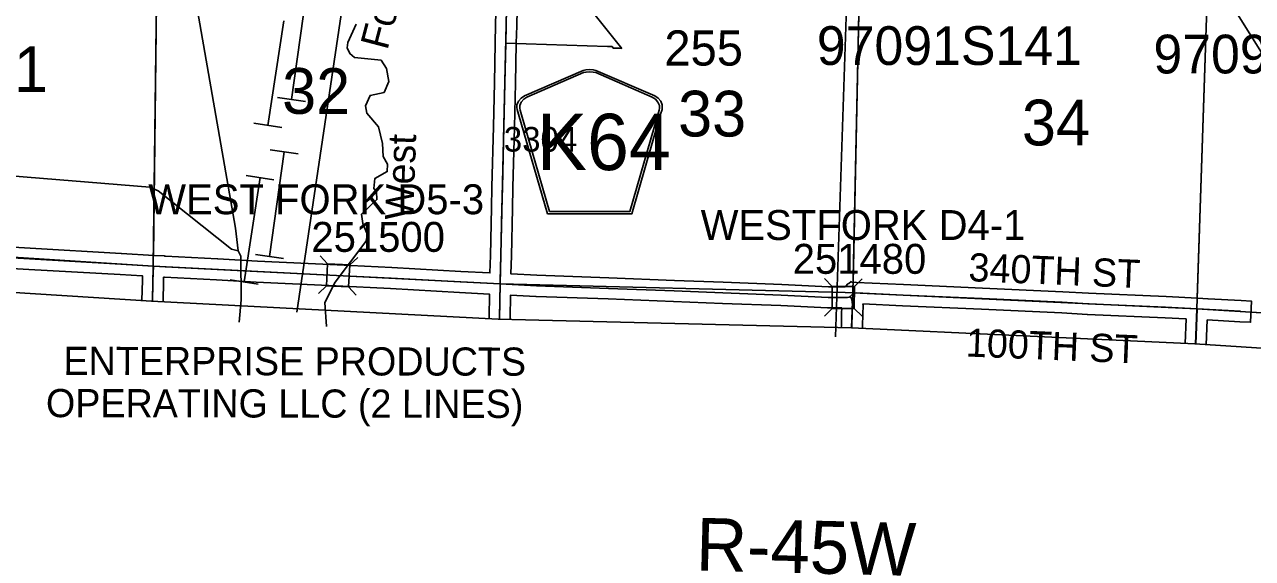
# Model space of a CAD drawing. Extents: x -157.2 to -99.3, y 12.2 to 46.2.
# Drawn here: x -134.532 to -131.046, y 15.921 to 17.437 of the extents above; entities that cross this region are included whole.
import ezdxf

# ---------------------------------------------------------------- set-up
doc = ezdxf.new("R2010")
doc.units = 0
for name, color, linetype in [('tdCoClipBndry', 7, 'Continuous'), ('tdCoCoAdjSecRdTxt', 7, 'Continuous'), ('tdCoCoBndry', 7, 'Continuous'), ('tdCoCoBndryPart', 7, 'Continuous'), ('tdCoCorpBndry', 7, 'Continuous'), ('tdCoCorpPopTxt', 7, 'Continuous'), ('tdCoHydroRiver', 7, 'Continuous'), ('tdCoHydroTxtLg', 7, 'Continuous'), ('tdCoPipe', 7, 'Continuous'), ('tdCoPipe1', 7, 'Continuous'), ('tdCoPipe2', 7, 'Continuous'), ('tdCoPipeTxt', 7, 'Continuous'), ('tdCoSecRdNmbr', 7, 'Continuous'), ('tdCoSecRdTxt', 7, 'Continuous'), ('tdCoSecRteBand', 7, 'Continuous'), ('tdCoSecRteCL', 7, 'Continuous'), ('tdCoSectLine', 7, 'Continuous'), ('tdCoSectLinePart', 7, 'Continuous'), ('tdCoSectNmbr', 7, 'Continuous'), ('tdCoShieldCoRteHrd', 7, 'Continuous'), ('tdCoStrucPriMaintName', 7, 'Continuous'), ('tdCoStrucSec', 7, 'Continuous'), ('tdCoStrucSecCoName', 7, 'Continuous'), ('tdCoStrucSecFHWANum', 7, 'Continuous'), ('tdCoSurfAsphalt', 7, 'Continuous'), ('tdCoSurfConc', 7, 'Continuous'), ('tdCoSurfEarth', 7, 'Continuous'), ('tdCoSurfGravel', 7, 'Continuous'), ('tdCoTwpBndryShd', 7, 'Continuous'), ('tdCoTwpRngTxt', 7, 'Continuous')]:
    doc.layers.add(name, color=color, linetype=linetype)

msp = doc.modelspace()

# ---------------------------------------------------------------- linework, layer by layer
at = {"layer": 'tdCoClipBndry'}
msp.add_lwpolyline([(-122.302, 16.1905), (-125.2749, 16.2789), (-127.2441, 16.3602), (-128.2341, 16.3892), (-129.2216, 16.4019), (-131.209, 16.5298), (-132.1838, 16.5754), (-133.1873, 16.6004), (-134.1718, 16.6514), (-135.1611, 16.7141)], dxfattribs=at)
at = {"layer": 'tdCoCoBndry'}
msp.add_lwpolyline([(-135.1553, 16.8138), (-134.1666, 16.7512), (-133.1821, 16.7002), (-132.2019, 16.6758), (-132.1802, 16.6753), (-131.2035, 16.6296), (-130.2056, 16.5679), (-129.2203, 16.5019), (-128.232, 16.4892), (-127.2406, 16.4601), (-126.2534, 16.4199), (-125.2718, 16.3788), (-124.2853, 16.348)], dxfattribs=at)
at = {"layer": 'tdCoCoBndryPart'}
msp.add_lwpolyline([(-131.0502, 16.6201), (-130.2056, 16.5679), (-129.6683, 16.5319)], dxfattribs=at)
at = {"layer": 'tdCoCorpBndry'}
msp.add_lwpolyline([(-132.8359, 17.3694), (-132.8426, 17.3696), (-132.8607, 17.3701), (-132.8642, 17.3744), (-132.8768, 17.3749), (-133.1659, 17.3844), (-133.1648, 17.4345), (-133.1625, 17.5325), (-133.1605, 17.6197), (-133.1601, 17.6388), (-133.1539, 17.6384), (-133.1371, 17.6477), (-133.0754, 17.6385), (-133.049, 17.6358)], close=True, dxfattribs=at)
at = {"layer": 'tdCoHydroRiver'}
for points in [[(-132.2292, 16.5498), (-132.1404, 19.2211)], [(-131.1696, 19.1917), (-131.1706, 18.9975), (-131.1548, 18.0351), (-131.1479, 17.6289), (-131.1402, 17.5702), (-131.1299, 17.5431), (-131.1208, 17.5318), (-131.1211, 17.5207), (-131.0201, 17.3581), (-130.8557, 17.1036), (-130.8545, 17.0925), (-130.8001, 17.0118), (-130.7907, 17.0084)], [(-134.107, 17.8578), (-133.9334, 16.8591), (-133.9258, 16.7941)], [(-133.6753, 16.5796), (-133.6793, 16.6476), (-133.6507, 16.7052), (-133.5636, 16.821), (-133.5582, 16.8398), (-133.5715, 16.8718), (-133.5754, 16.8987), (-133.5316, 16.94), (-133.5325, 16.9622), (-133.5401, 16.9719), (-133.5376, 17.0002), (-133.5023, 17.0197), (-133.5017, 17.0402), (-133.5137, 17.0627), (-133.5157, 17.0991), (-133.5269, 17.1468), (-133.5605, 17.1857), (-133.5646, 17.2064), (-133.5511, 17.236), (-133.5114, 17.2443), (-133.4978, 17.2754), (-133.5046, 17.312), (-133.5197, 17.3361), (-133.5952, 17.3431), (-133.6091, 17.3546), (-133.6165, 17.3706), (-133.6144, 17.3864), (-133.5908, 17.4378)], [(-134.6184, 17.0108), (-134.1761, 16.9754), (-134.1527, 16.9652), (-133.9446, 16.7994), (-133.9258, 16.7941)], [(-133.9258, 16.7941), (-133.9184, 16.7796), (-133.9174, 16.6548), (-133.9233, 16.5915)]]:
    msp.add_lwpolyline(points, dxfattribs=at)
at = {"layer": 'tdCoPipe'}
msp.add_lwpolyline([(-133.759, 16.6205), (-133.5865, 17.7778), (-133.4655, 18.0471), (-133.3685, 18.1297), (-133.2951, 18.596), (-133.1374, 20.0968), (-132.9167, 20.1674), (-132.8765, 20.8382), (-131.6756, 21.8898), (-131.4423, 22.6481), (-130.9379, 23.6667), (-130.3462, 24.8998), (-130.3405, 25.1948), (-130.2487, 25.3673), (-130.2364, 26.2904), (-130.2373, 27.9658), (-130.2301, 29.1582), (-130.2142, 30.4341), (-130.1913, 32.2243), (-130.16, 33.6013), (-130.1464, 33.8322), (-130.2014, 34.2309), (-130.2039, 34.9469)], dxfattribs=at)
at = {"layer": 'tdCoPipe1'}
for p, q in [((-133.8808, 17.1568), (-133.8015, 17.1448)), ((-133.9033, 17.0085), (-133.824, 16.9964)), ((-133.9483, 16.7119), (-133.869, 16.6998))]:
    msp.add_line(p, q, dxfattribs=at)
for points in [[(-133.7961, 17.4474), (-133.8411, 17.1508)], [(-133.8636, 17.0025), (-133.9086, 16.7059)]]:
    msp.add_lwpolyline(points, dxfattribs=at)
at = {"layer": 'tdCoPipe2'}
for p, q in [((-133.814, 17.2298), (-133.7346, 17.2186)), ((-133.835, 17.0813), (-133.7556, 17.0701)), ((-133.8768, 16.7842), (-133.7974, 16.773))]:
    msp.add_line(p, q, dxfattribs=at)
for points in [[(-133.7325, 17.5213), (-133.7743, 17.2242)], [(-133.7953, 17.0757), (-133.8371, 16.7786)]]:
    msp.add_lwpolyline(points, dxfattribs=at)
at = {"layer": 'tdCoSecRteBand'}
for points in [[(-134.7125, 16.813), (-134.5166, 16.8017), (-134.5166, 16.8017), (-134.5166, 16.8017), (-134.2575, 16.7866), (-134.2574, 16.7866), (-134.2574, 16.7866), (-134.1649, 16.7812), (-134.1353, 16.7802), (-134.1353, 16.7795), (-134.1318, 16.7793), (-133.9839, 16.7716), (-133.9839, 16.7716), (-133.9838, 16.7716), (-133.8712, 16.7654), (-133.6447, 16.7546), (-133.4898, 16.7472), (-133.4897, 16.7472), (-133.4895, 16.7472), (-133.2938, 16.7359), (-133.211, 16.7317), (-133.2097, 16.7814), (-133.2067, 16.9162), (-133.2054, 16.9752), (-133.2054, 16.9752), (-133.2054, 16.9753), (-133.2011, 17.1471), (-133.1983, 17.2717), (-133.1959, 17.3847), (-133.1959, 17.3847), (-133.1959, 17.385), (-133.1948, 17.4351), (-133.1948, 17.4351), (-133.1948, 17.4352), (-133.1905, 17.6204)], [(-133.1305, 17.619), (-133.1348, 17.4338), (-133.1359, 17.3841), (-133.1359, 17.3841), (-133.1359, 17.3837), (-133.1384, 17.2704), (-133.1384, 17.2704), (-133.1384, 17.2704), (-133.1412, 17.1457), (-133.1412, 17.1456), (-133.1412, 17.1456), (-133.1455, 16.9739), (-133.1467, 16.9149), (-133.1467, 16.9148), (-133.1467, 16.9148), (-133.1498, 16.78), (-133.1498, 16.78), (-133.1498, 16.7799), (-133.1511, 16.7287), (-133.1502, 16.7287), (-133.0776, 16.725), (-132.8732, 16.7176), (-132.8731, 16.7176), (-132.8731, 16.7176), (-132.6869, 16.7105), (-132.6869, 16.7105), (-132.6869, 16.7105), (-132.5483, 16.705), (-132.3823, 16.6986), (-132.3822, 16.6986), (-132.3821, 16.6986), (-132.2498, 16.6922), (-132.2031, 16.692), (-132.2008, 16.6943), (-132.1944, 16.7007), (-132.1918, 16.7012), (-132.1849, 16.7072), (-132.1825, 16.7045), (-132.1796, 16.7064), (-132.178, 16.704), (-132.1772, 16.7042), (-132.1735, 16.705), (-132.1697, 16.7048), (-132.0364, 16.6984), (-131.8123, 16.6888), (-131.8123, 16.6888), (-131.8122, 16.6888), (-131.5846, 16.6782), (-131.5844, 16.6781), (-131.5843, 16.6781), (-131.5117, 16.674), (-131.291, 16.6644), (-131.2908, 16.6643), (-131.2907, 16.6643), (-131.2017, 16.6596), (-131.172, 16.6584), (-131.172, 16.658), (-131.0781, 16.653), (-131.0481, 16.6514), (-131.0513, 16.5915), (-131.0813, 16.5931), (-131.1743, 16.598), (-131.177, 16.5277)], [(-134.199, 16.6531), (-134.1976, 16.7109), (-134.1976, 16.711), (-134.1976, 16.7112), (-134.1972, 16.723), (-134.1979, 16.723), (-134.2609, 16.7267), (-134.5201, 16.7418), (-134.7162, 16.7531)], [(-133.2134, 16.6017), (-133.2133, 16.6055), (-133.2122, 16.6717), (-133.297, 16.6759), (-133.2971, 16.6759), (-133.2972, 16.6759), (-133.4928, 16.6873), (-133.6476, 16.6947), (-133.6476, 16.6947), (-133.8742, 16.7055), (-133.8743, 16.7055), (-133.8744, 16.7055), (-133.9871, 16.7117), (-134.135, 16.7193), (-134.1351, 16.7193), (-134.1352, 16.7193), (-134.1373, 16.7195), (-134.1376, 16.7093), (-134.1391, 16.6497)], [(-132.2134, 16.5761), (-132.2131, 16.5815), (-132.2124, 16.6169), (-132.2124, 16.6172), (-132.2124, 16.6176), (-132.2118, 16.6321), (-132.2507, 16.6322), (-132.2514, 16.6322), (-132.252, 16.6323), (-132.3848, 16.6387), (-132.5506, 16.6451), (-132.5506, 16.6451), (-132.5506, 16.6451), (-132.6892, 16.6505), (-132.8754, 16.6577), (-133.08, 16.6651), (-133.0802, 16.6651), (-133.0804, 16.6651), (-133.1522, 16.6687), (-133.1533, 16.6043), (-133.1533, 16.6042), (-133.1533, 16.6041), (-133.1534, 16.5995)], [(-131.2369, 16.5311), (-131.2342, 16.6012), (-131.2347, 16.6013), (-131.2937, 16.6044), (-131.5145, 16.614), (-131.5147, 16.614), (-131.515, 16.614), (-131.5875, 16.6182), (-131.8149, 16.6288), (-132.039, 16.6384), (-132.0391, 16.6384), (-132.0392, 16.6384), (-132.1516, 16.6438), (-132.1515, 16.6411), (-132.1514, 16.6398), (-132.1514, 16.6385), (-132.1524, 16.6154), (-132.1532, 16.5799), (-132.1532, 16.5796), (-132.1532, 16.5792), (-132.1534, 16.574)]]:
    msp.add_lwpolyline(points, dxfattribs=at)
at = {"layer": 'tdCoSecRteCL'}
for p, q in [((-131.207, 16.5297), (-131.2031, 16.6296)), ((-131.2031, 16.6296), (-131.0797, 16.623))]:
    msp.add_line(p, q, dxfattribs=at)
for points in [[(-133.1817, 16.7002), (-133.1815, 16.7103), (-133.1798, 16.7807), (-133.1767, 16.9155), (-133.1754, 16.9745), (-133.1711, 17.1464), (-133.1684, 17.271), (-133.1659, 17.3844), (-133.1659, 17.3844), (-133.1648, 17.4345), (-133.1605, 17.6197), (-133.1601, 17.6388), (-133.1596, 17.6635), (-133.1583, 17.7272), (-133.1558, 17.8267), (-133.1553, 17.8476), (-133.1536, 17.9159), (-133.1519, 17.9877), (-133.1516, 17.997), (-133.1506, 18.0482), (-133.1504, 18.0533), (-133.149, 18.0886), (-133.1473, 18.1331), (-133.146, 18.1781)], [(-136.1292, 16.8661), (-136.0182, 16.86), (-135.7743, 16.8465), (-135.6318, 16.8388), (-135.4777, 16.8309), (-135.2594, 16.8203), (-135.1525, 16.8137), (-135.108, 16.8109), (-134.7144, 16.7831), (-134.5184, 16.7717), (-134.2592, 16.7567), (-134.1662, 16.7512)], [(-134.169, 16.6513), (-134.1676, 16.7102), (-134.1662, 16.7512)], [(-134.1662, 16.7512), (-134.1334, 16.7493), (-133.9855, 16.7417), (-133.8728, 16.7355), (-133.6461, 16.7246), (-133.4913, 16.7172), (-133.2955, 16.7059), (-133.1817, 16.7002)], [(-133.1834, 16.6003), (-133.1833, 16.6048), (-133.1817, 16.7002)], [(-133.1817, 16.7002), (-133.0789, 16.695), (-132.8743, 16.6876), (-132.6881, 16.6805), (-132.5495, 16.6751), (-132.3835, 16.6687), (-132.2506, 16.6622), (-132.1958, 16.662), (-132.1909, 16.6625), (-132.1881, 16.6649)], [(-132.1881, 16.6649), (-132.1857, 16.6669), (-132.1796, 16.6731), (-132.1712, 16.6748), (-132.0378, 16.6684), (-131.8136, 16.6588), (-131.586, 16.6482), (-131.5132, 16.644), (-131.2923, 16.6344), (-131.2031, 16.6296)], [(-132.1834, 16.5754), (-132.1831, 16.5805), (-132.1824, 16.6163), (-132.1814, 16.6397), (-132.1819, 16.6506), (-132.1844, 16.6585), (-132.1864, 16.6622), (-132.1881, 16.6649)]]:
    msp.add_lwpolyline(points, dxfattribs=at)
at = {"layer": 'tdCoSectLine'}
for points in [[(-134.1666, 16.7512), (-134.1544, 17.7403)], [(-133.1595, 17.684), (-133.1821, 16.7002)], [(-132.1802, 16.6753), (-132.16, 17.6471)], [(-131.2035, 16.6296), (-131.1717, 17.6002)], [(-135.1553, 16.8138), (-134.1666, 16.7512)], [(-134.1691, 16.6513), (-134.1666, 16.7512)], [(-134.1666, 16.7512), (-133.1821, 16.7002)], [(-133.1841, 16.6003), (-133.1821, 16.7002)], [(-133.1821, 16.7002), (-132.2019, 16.6758), (-132.1802, 16.6753)], [(-132.1847, 16.5754), (-132.1802, 16.6753)], [(-132.1802, 16.6753), (-131.2035, 16.6296)], [(-131.2074, 16.5297), (-131.2035, 16.6296)], [(-131.2035, 16.6296), (-130.2056, 16.5679)]]:
    msp.add_lwpolyline(points, dxfattribs=at)
at = {"layer": 'tdCoSectLinePart'}
for points in [[(-134.1662, 16.7812), (-134.1544, 17.7403)], [(-132.1796, 16.7031), (-132.16, 17.6471)], [(-131.2025, 16.6596), (-131.1717, 17.6002)], [(-131.0502, 16.6201), (-130.2056, 16.5679)]]:
    msp.add_lwpolyline(points, dxfattribs=at)
at = {"layer": 'tdCoShieldCoRteHrd'}
for points in [[(-133.0475, 16.8994), (-133.1295, 17.1823), (-133.1334, 17.1954), (-133.1341, 17.2013), (-133.1341, 17.2091), (-133.1299, 17.2195), (-133.1226, 17.2279), (-133.113, 17.2346), (-132.9457, 17.307), (-132.9382, 17.3086), (-132.9278, 17.3095), (-132.9174, 17.3086), (-132.9098, 17.307), (-132.7426, 17.2346), (-132.733, 17.2279), (-132.7257, 17.2195), (-132.7215, 17.2091), (-132.7215, 17.2013), (-132.7222, 17.1954), (-132.7261, 17.1823), (-132.808, 16.8994)], [(-133.0417, 16.9057), (-133.1214, 17.181), (-133.1251, 17.1936), (-133.1258, 17.1993), (-133.1258, 17.2068), (-133.1218, 17.2167), (-133.1148, 17.2248), (-133.1056, 17.2312), (-132.945, 17.3007), (-132.9378, 17.3023), (-132.9278, 17.3031), (-132.9178, 17.3023), (-132.9106, 17.3007), (-132.75, 17.2312), (-132.7408, 17.2248), (-132.7338, 17.2167), (-132.7297, 17.2068), (-132.7297, 17.1993), (-132.7304, 17.1936), (-132.7342, 17.181), (-132.8139, 16.9057)]]:
    msp.add_lwpolyline(points, close=True, dxfattribs=at)
at = {"layer": 'tdCoStrucSec'}
for p, q in [((-133.6716, 16.7572), (-133.6926, 16.7803)), ((-133.609, 16.7542), (-133.5859, 16.7752)), ((-132.2387, 16.6935), (-132.2608, 16.7157)), ((-132.1761, 16.6932), (-132.1539, 16.7152)), ((-133.6745, 16.6946), (-133.6977, 16.6736)), ((-133.612, 16.6917), (-133.591, 16.6685)), ((-132.239, 16.6309), (-132.2612, 16.6089)), ((-132.1764, 16.6306), (-132.1544, 16.6084))]:
    msp.add_line(p, q, dxfattribs=at)
for points in [[(-133.6716, 16.7572), (-133.609, 16.7542), (-133.612, 16.6917), (-133.6745, 16.6946)], [(-132.2387, 16.6935), (-132.1761, 16.6932), (-132.1764, 16.6306), (-132.239, 16.6309)]]:
    msp.add_lwpolyline(points, close=True, dxfattribs=at)
at = {"layer": 'tdCoSurfAsphalt'}
msp.add_lwpolyline([(-133.1834, 16.6003), (-133.1833, 16.6048), (-133.1817, 16.7002)], dxfattribs=at)
at = {"layer": 'tdCoSurfConc'}
msp.add_line((-133.1659, 17.3844), (-133.1659, 17.3844), dxfattribs=at)
for points in [[(-133.1659, 17.3844), (-133.1648, 17.4345), (-133.1605, 17.6197), (-133.1601, 17.6388)], [(-133.1817, 16.7002), (-133.1815, 16.7103), (-133.1798, 16.7807), (-133.1767, 16.9155), (-133.1754, 16.9745), (-133.1711, 17.1464), (-133.1684, 17.271), (-133.1659, 17.3844)]]:
    msp.add_lwpolyline(points, dxfattribs=at)
at = {"layer": 'tdCoSurfEarth'}
msp.add_line((-131.2031, 16.6296), (-131.0797, 16.623), dxfattribs=at)
msp.add_lwpolyline([(-135.1525, 16.8137), (-135.108, 16.8109), (-134.7144, 16.7831), (-134.5184, 16.7717), (-134.2592, 16.7567), (-134.1662, 16.7512)], dxfattribs=at)
at = {"layer": 'tdCoSurfGravel'}
msp.add_line((-131.207, 16.5297), (-131.2031, 16.6296), dxfattribs=at)
for points in [[(-134.169, 16.6513), (-134.1676, 16.7102), (-134.1662, 16.7512)], [(-134.1662, 16.7512), (-134.1334, 16.7493), (-133.9855, 16.7417), (-133.8728, 16.7355), (-133.6461, 16.7246), (-133.4913, 16.7172), (-133.2955, 16.7059), (-133.1817, 16.7002), (-133.0789, 16.695), (-132.8743, 16.6876), (-132.6881, 16.6805), (-132.5495, 16.6751), (-132.3835, 16.6687), (-132.2506, 16.6622), (-132.1958, 16.662), (-132.1909, 16.6625), (-132.1881, 16.6649)], [(-132.1881, 16.6649), (-132.1857, 16.6669), (-132.1796, 16.6731), (-132.1712, 16.6748), (-132.0378, 16.6684), (-131.8136, 16.6588), (-131.586, 16.6482), (-131.5132, 16.644), (-131.2923, 16.6344), (-131.2031, 16.6296)], [(-132.1834, 16.5754), (-132.1831, 16.5805), (-132.1824, 16.6163), (-132.1814, 16.6397), (-132.1819, 16.6506), (-132.1844, 16.6585), (-132.1864, 16.6622), (-132.1881, 16.6649)]]:
    msp.add_lwpolyline(points, dxfattribs=at)
at = {"layer": 'tdCoTwpBndryShd'}
msp.add_lwpolyline([(-124.2853, 16.348), (-125.2718, 16.3788), (-126.2534, 16.4199), (-127.2406, 16.4601), (-128.232, 16.4892), (-129.2203, 16.5019), (-130.2056, 16.5679), (-131.2035, 16.6296), (-132.1802, 16.6753), (-132.2019, 16.6758), (-133.1821, 16.7002), (-134.1666, 16.7512), (-135.1553, 16.8138)], dxfattribs=at)

# ---------------------------------------------------------------- texts
at = {"layer": 'tdCoCoAdjSecRdTxt'}
msp.add_text('100TH ST', height=0.08, rotation=357.6693, dxfattribs=at).set_placement((-131.8606, 16.4944))
at = {"layer": 'tdCoCorpPopTxt'}
msp.add_text('255', height=0.1, dxfattribs=at).set_placement((-132.7156, 17.3206))
at = {"layer": 'tdCoHydroTxtLg'}
for s, rotation, p in [('Fork', 75.2532, (-133.5022, 17.3621)), ('West', 87.9852, (-133.4288, 16.881))]:
    msp.add_text(s, height=0.08, rotation=rotation, dxfattribs=at).set_placement(p)
at = {"layer": 'tdCoPipeTxt'}
for s, p in [('ENTERPRISE PRODUCTS', (-134.4219, 16.442)), ('OPERATING LLC (2 LINES)', (-134.4715, 16.322))]:
    msp.add_text(s, height=0.08, rotation=359.8972, dxfattribs=at).set_placement(p)
at = {"layer": 'tdCoSecRdNmbr'}
msp.add_text('3304', height=0.07, rotation=359.8993, dxfattribs=at).set_placement((-133.1714, 17.0763))
at = {"layer": 'tdCoSecRdTxt'}
msp.add_text('340TH ST', height=0.08, rotation=357.6693, dxfattribs=at).set_placement((-131.8532, 16.7084))
at = {"layer": 'tdCoSectNmbr'}
for s, rotation, p in [('31', 359.8981, (-134.6592, 17.2455)), ('32', 359.8988, (-133.801, 17.1836)), ('33', 359.8996, (-132.6767, 17.1193)), ('34', 359.9004, (-131.7005, 17.0939))]:
    msp.add_text(s, height=0.13, rotation=rotation, dxfattribs=at).set_placement(p)
at = {"layer": 'tdCoShieldCoRteHrd'}
msp.add_text('K64', height=0.16, dxfattribs=at).set_placement((-133.078, 17.0237))
at = {"layer": 'tdCoStrucPriMaintName'}
for s, p in [('97091S141', (-132.2827, 17.3224)), ('97094S141', (-131.327, 17.2983))]:
    msp.add_text(s, height=0.11, dxfattribs=at).set_placement(p)
at = {"layer": 'tdCoStrucSecCoName'}
for s, p in [('WEST FORK D5-3', (-134.181, 16.8984)), ('WESTFORK D4-1', (-132.6125, 16.8252))]:
    msp.add_text(s, height=0.085, dxfattribs=at).set_placement(p)
at = {"layer": 'tdCoStrucSecFHWANum'}
for s, p in [('251500', (-133.7178, 16.7915)), ('251480', (-132.3512, 16.7291))]:
    msp.add_text(s, height=0.085, dxfattribs=at).set_placement(p)
at = {"layer": 'tdCoTwpRngTxt'}
msp.add_text('R-45W', height=0.15, rotation=358.5755, dxfattribs=at).set_placement((-132.6272, 15.8864))

doc.saveas('drawing.dxf')
